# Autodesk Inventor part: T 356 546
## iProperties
Company: Mayer & Müller AG Schaltgeräte
Created: 2006-01
Part Number: T 356 546
Material: 1.0718.07
Document SubType Name: Modeling
Designer: I.Baliuc
Manufacturer: Standard
Standards Organization: Custom
Description: Bolzen
Density: 7.84 g/cm^3
HalbzeugNorm: DIN 176
Zweck: Haubenbefestigung (links)
Abmessung: Skt 11
Author: T.Messerschmitt
Revision Number: 356546
Keywords: 266414
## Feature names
1. Extrusion2
2. Bohrung_M6x12 [Hole]
3. Extrusion3
4. Fase1 [Chamfer]
